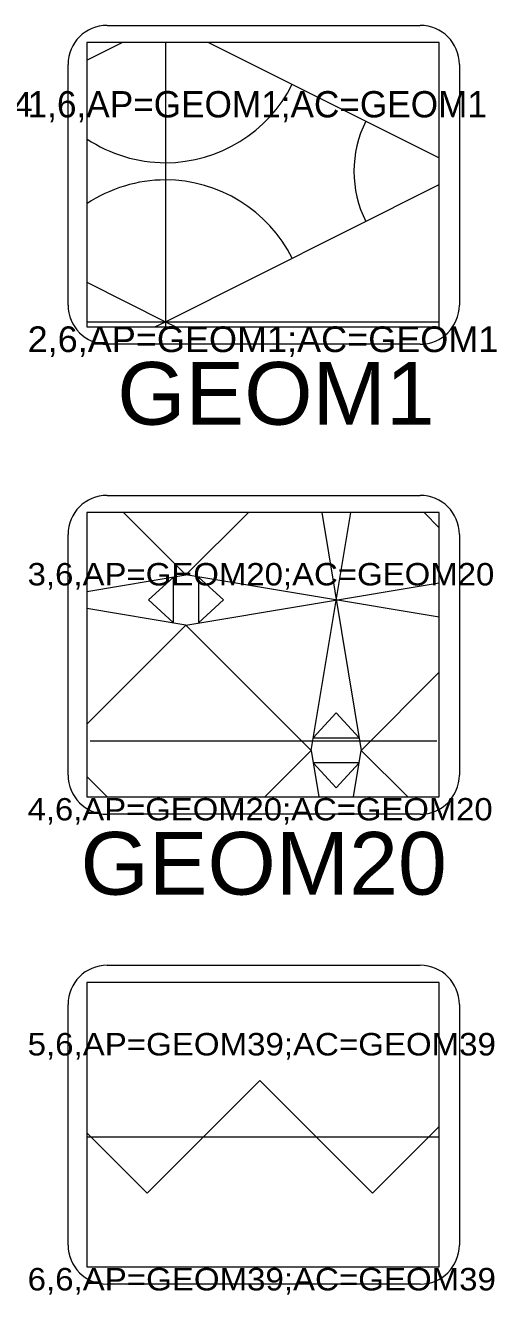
# Model space of a CAD drawing. Extents: x 95935 to 95946.4, y 95971.2 to 95974.7.
# Drawn here: x 95938.031 to 95938.633, y 95973.111 to 95974.732 of the extents above; entities that cross this region are included whole.
import ezdxf
from ezdxf.enums import TextEntityAlignment as Align

# ---------------------------------------------------------------- set-up
doc = ezdxf.new("R2010")
doc.units = 0
doc.header["$LTSCALE"] = 0.032
for name, color, linetype, lineweight in [('1', 7, 'Continuous', 13), ('2', 7, 'Continuous', 13), ('25', 7, 'Continuous', 13), ('6', 7, 'Continuous', 13), ('63', 7, 'Continuous', 13)]:
    doc.layers.add(name, color=color, linetype=linetype, lineweight=lineweight)
doc.layers.add('20', color=7, linetype='Continuous')

msp = doc.modelspace()

# ---------------------------------------------------------------- linework, layer by layer
at = {"layer": '1'}
for p, q in [((95938.1357, 95974.7318), (95938.5357, 95974.7318)), ((95938.0857, 95974.3747), (95938.0857, 95974.6818)), ((95938.5857, 95974.6818), (95938.5857, 95974.3747)), ((95938.5357, 95974.3247), (95938.1357, 95974.3247)), ((95938.1357, 95974.1318), (95938.5357, 95974.1318)), ((95938.0857, 95973.7747), (95938.0857, 95974.0818)), ((95938.5857, 95974.0818), (95938.5857, 95973.7747)), ((95938.5357, 95973.7247), (95938.1357, 95973.7247)), ((95938.1357, 95973.5318), (95938.5357, 95973.5318)), ((95938.0857, 95973.1747), (95938.0857, 95973.4818)), ((95938.5857, 95973.4818), (95938.5857, 95973.1747)), ((95938.5357, 95973.1247), (95938.1357, 95973.1247))]:
    msp.add_line(p, q, dxfattribs=at)
for centre, start, end in [((95938.1357, 95974.6818), 90, 180), ((95938.5357, 95974.6818), 0, 90), ((95938.1357, 95974.3747), 180, 270), ((95938.5357, 95974.3747), 270, 0), ((95938.1357, 95974.0818), 90, 180), ((95938.5357, 95974.0818), 0, 90), ((95938.1357, 95973.7747), 180, 270), ((95938.5357, 95973.7747), 270, 0), ((95938.1357, 95973.4818), 90, 180), ((95938.5357, 95973.4818), 0, 90), ((95938.1357, 95973.1747), 180, 270), ((95938.5357, 95973.1747), 270, 0)]:
    msp.add_arc(centre, 0.05, start, end, dxfattribs=at)
at = {"layer": '2'}
for points in [[(95938.5601, 95974.7099), (95938.1097, 95974.7099), (95938.1097, 95974.3468), (95938.5601, 95974.3468)], [(95938.5601, 95974.1099), (95938.1097, 95974.1099), (95938.1097, 95973.7468), (95938.5601, 95973.7468)], [(95938.5601, 95973.5099), (95938.1097, 95973.5099), (95938.1097, 95973.1468), (95938.5601, 95973.1468)]]:
    msp.add_lwpolyline(points, close=True, dxfattribs=at)
at = {"layer": '25'}
msp.add_line((95938.5569, 95973.8178), (95938.1141, 95973.8178), dxfattribs=at)
at = {"layer": '6'}
for p, q in [((95938.1097, 95974.6873), (95938.155, 95974.7099)), ((95938.2102, 95974.7099), (95938.2102, 95974.3468)), ((95938.2654, 95974.7099), (95938.5601, 95974.5626)), ((95938.2102, 95974.3535), (95938.5601, 95974.5285)), ((95938.1097, 95974.4038), (95938.2102, 95974.3535)), ((95938.1097, 95974.3535), (95938.2102, 95974.3535)), ((95938.1968, 95974.3468), (95938.2102, 95974.3535)), ((95938.2102, 95974.3535), (95938.2236, 95974.3468)), ((95938.2102, 95974.3535), (95938.5601, 95974.3535)), ((95938.1567, 95974.1099), (95938.2364, 95974.0302)), ((95938.3964, 95973.8062), (95938.447, 95974.1099)), ((95938.4098, 95974.1099), (95938.4604, 95973.8062)), ((95938.5407, 95974.1099), (95938.5601, 95974.0905)), ((95938.1097, 95974.0091), (95938.2364, 95974.0302)), ((95938.2364, 95973.9662), (95938.5601, 95974.0202)), ((95938.2364, 95973.9662), (95938.1097, 95973.9873)), ((95938.2364, 95973.9662), (95938.1097, 95973.8395)), ((95938.3964, 95973.8062), (95938.2364, 95973.9662)), ((95938.5601, 95973.9059), (95938.4604, 95973.8062)), ((95938.337, 95973.7468), (95938.3964, 95973.8062)), ((95938.3964, 95973.8062), (95938.4063, 95973.7468)), ((95938.4505, 95973.7468), (95938.4604, 95973.8062)), ((95938.4604, 95973.8062), (95938.5198, 95973.7468)), ((95938.1097, 95973.7729), (95938.1358, 95973.7468)), ((95938.1097, 95973.318), (95938.1868, 95973.2409)), ((95938.1097, 95973.3129), (95938.5601, 95973.3129)), ((95938.5468, 95973.3129), (95938.5601, 95973.3262))]:
    msp.add_line(p, q, dxfattribs=at)
for points in [[(95938.5601, 95973.9763), (95938.2364, 95974.0302), (95938.3161, 95974.1099)], [(95938.1868, 95973.2409), (95938.2588, 95973.3129), (95938.3308, 95973.3849), (95938.4748, 95973.2409), (95938.5468, 95973.3129)]]:
    msp.add_lwpolyline(points, dxfattribs=at)
for points in [[(95938.2204, 95973.9689), (95938.2204, 95974.0275), (95938.1884, 95973.9982)], [(95938.2524, 95974.0275), (95938.2524, 95973.9689), (95938.2844, 95973.9982)], [(95938.3991, 95973.8222), (95938.4577, 95973.8222), (95938.4284, 95973.8542)], [(95938.4577, 95973.7902), (95938.3991, 95973.7902), (95938.4284, 95973.7582)]]:
    msp.add_lwpolyline(points, close=True, dxfattribs=at)
for centre, radius, start, end in [((95938.2102, 95974.7375), 0.181, 270, 333.4349), ((95938.5942, 95974.5455), 0.1431, 153.4349, 206.565), ((95938.2102, 95974.7375), 0.181, 236.2778, 270), ((95938.2102, 95974.3535), 0.181, 90, 123.7222), ((95938.2102, 95974.3535), 0.181, 26.5651, 90)]:
    msp.add_arc(centre, radius, start, end, dxfattribs=at)

# ---------------------------------------------------------------- texts
at = {"layer": '20', "width": 1.05}
for s, p in [(' GEOM1', (95938.3358, 95974.222)), ('GEOM20', (95938.3357, 95973.622))]:
    msp.add_text(s, height=0.08, dxfattribs=at).set_placement(p, align=Align.CENTER)
at = {"layer": '63'}
for s, height, width, p in [('1,5,AP=INOUT4;AC=INOUT4', 0.0313, 1.1, (95937.4341, 95974.6154)), ('2,6,AP=GEOM1;AC=GEOM1', 0.0328, 1.05, (95938.0341, 95974.3147)), ('3,6,AP=GEOM20;AC=GEOM20', 0.0286, 1.1, (95938.0341, 95974.0168)), ('4,6,AP=GEOM20;AC=GEOM20', 0.0285, 1.1, (95938.0341, 95973.7168)), ('5,6,AP=GEOM39;AC=GEOM39', 0.0287, 1.1, (95938.0341, 95973.4167)), ('6,6,AP=GEOM39;AC=GEOM39', 0.0287, 1.1, (95938.0341, 95973.1167))]:
    msp.add_text(s, height=height, dxfattribs=dict(at, width=width)).set_placement(p)
msp.add_text('1,6,AP=GEOM1;AC=GEOM1', height=0.0336, dxfattribs=at).set_placement((95938.0341, 95974.6143))

doc.saveas('drawing.dxf')
